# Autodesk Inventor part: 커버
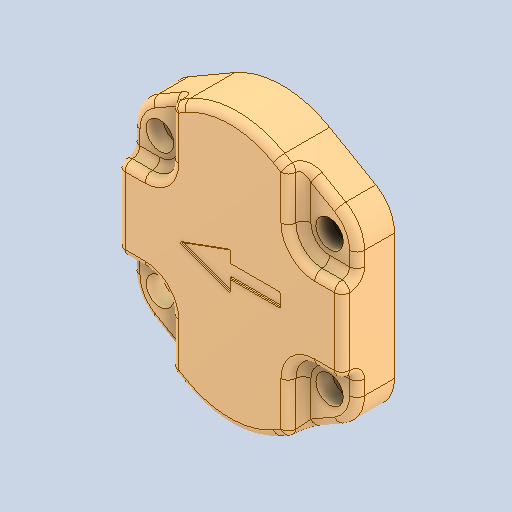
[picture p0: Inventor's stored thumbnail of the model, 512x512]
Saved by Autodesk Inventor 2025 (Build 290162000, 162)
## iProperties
Created: 2026-08
Part Number: 커버
Material: 알루미늄 6061
Document SubType Name: Modeling
Designer: KDI
Density: 2.7 g/cm^3
Appearance: 기본값
Author: jhkim
Sending System: Autodesk Inventor 2027
Preprocessor: ST-DEVELOPER v20.1
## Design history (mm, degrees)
feature "솔리드2"
node "솔리드1"
